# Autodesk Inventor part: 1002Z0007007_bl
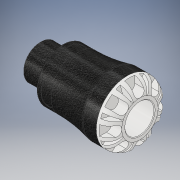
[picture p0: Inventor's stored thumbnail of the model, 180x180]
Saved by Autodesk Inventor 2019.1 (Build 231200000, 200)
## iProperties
Created: 2016-12
Part Number: 1002Z0007007_bl
Material: PVC-Piping
Description: PLASSON MALE ADAPTOR 3/4''CTS x 3/4''NPT SERIES 1
Document SubType Name: Modeling
Designer: KIM
Mass: 61.7504 g
Surface Area: 140.097 cm^2
Volume: 44.1074 cm^3
Density: 1.4 g/cm^3
Appearance: Black Cast
Author: KIM
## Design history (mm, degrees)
derived "1002Z.ipt"
feature "Solid1::1002Z.ipt" dims "ScaleForDerivedMember" = 10
tag "TaggingFeature1"
body "Solid1"
other parameters: "d0" = 75.946 [user parameter], "d1" = 20.16252 [user parameter], "d2" = 22.1 [user parameter], "d3" = 27.625 [user parameter], "d4" = 46.99 [user parameter], "d6" = 48.006 [user parameter], "d8" = 39.9415 [user parameter], "d13" = 7.746 [user parameter], "d14" = 7.746 [user parameter], "d15" = 0 [user parameter], "d17" = 360 deg [user parameter], "d19" = 8 deg [user parameter], "d20" = 0.442 [user parameter], "d21" = 0.442 [user parameter], "d22" = 8 deg [user parameter], "d24" = 0 [user parameter], "d26" = 360 deg [user parameter], "d32" = 0.925 [user parameter], "d33" = 4.699 [user parameter], "d34" = 26.441 [user parameter], "d35" = 2.7625 [user parameter], "d38" = 17.018 [user parameter], "d39" = 0.79323 [user parameter], "d42" = 7.735 [user parameter], "d43" = 5.083 [user parameter], "d45" = 15.18216 [user parameter], "d46" = 0 [user parameter], "d59" = 360 deg [user parameter], "d61" = 6.57475 [user parameter], "d62" = 0.442 [user parameter], "d64" = 0 [user parameter], "d65" = 0.4699 [user parameter], "d_" = 22.1 [user parameter], "E_" = 46.99 [user parameter], "H_" = 75.946 [user parameter], "l_" = 48.006 [user parameter], "R_" = 26.441 [user parameter], "l_2" = 17.018 [user parameter], "d9" = 9.6825 [user parameter], "d11" = 46.99 [user parameter], "d12" = 27.625 [user parameter]
